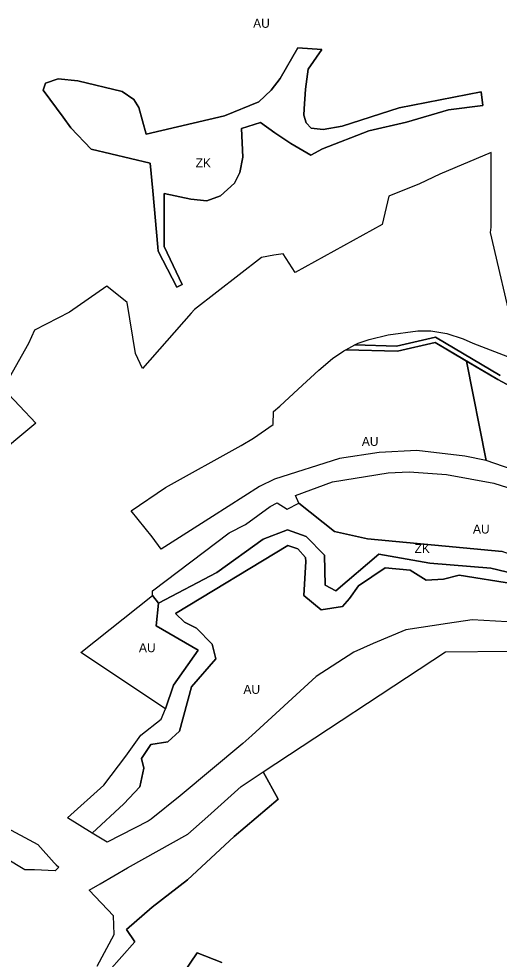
# Model space of a CAD drawing. Extents: x -521261 to -517465, y -1182764 to -1179456.
# Drawn here: x -518978 to -518710, y -1182068 to -1181544 of the extents above; entities that cross this region are included whole.
import ezdxf

# ---------------------------------------------------------------- set-up
doc = ezdxf.new("R2010")
doc.units = 0
for name, color, linetype in [('90640013', 7, 'Continuous'), ('90710013', 7, 'Continuous'), ('90750013', 7, 'Continuous')]:
    doc.layers.add(name, color=color, linetype=linetype)

msp = doc.modelspace()

# ---------------------------------------------------------------- linework, layer by layer
at = {"layer": '90640013'}
for points in [[(-518701.51, -1181750.01), (-518711.17, -1181744.79), (-518746.18, -1181724.23), (-518767.13, -1181729.02), (-518795.95, -1181728.17), (-518790.82, -1181725.54), (-518767.59, -1181726.19), (-518745.97, -1181721.22), (-518709.95, -1181742.54)], [(-518702.42, -1181858.59), (-518732.72, -1181853.68), (-518741.51, -1181856.01), (-518751.19, -1181856.52), (-518760.12, -1181851.01), (-518773.96, -1181849.7), (-518788.84, -1181859.75), (-518793.87, -1181866.71), (-518797.84, -1181871.11), (-518809.69, -1181873.09), (-518819.36, -1181864.98), (-518818.14, -1181846.17), (-518818.45, -1181843.81), (-518822.57, -1181839.04), (-518828.29, -1181837.22), (-518890.78, -1181874.99), (-518885.85, -1181879.81), (-518879.15, -1181883.26), (-518870.33, -1181892.11), (-518868.33, -1181900.31), (-518881.83, -1181915.88), (-518888.56, -1181940.6), (-518895.16, -1181946.6), (-518904.62, -1181947.99), (-518909.68, -1181955.8), (-518908.47, -1181961.1), (-518910.69, -1181971.61), (-518919.62, -1181981.1), (-518937.284, -1181997.298), (-518951.03, -1181988.87), (-518930.7, -1181970.59), (-518918.49, -1181954.45), (-518910.09, -1181942.77), (-518898.82, -1181933.95), (-518896.41, -1181928.2), (-518892.01, -1181914.91), (-518878.22, -1181895.5), (-518901.61, -1181881.85), (-518900.37, -1181869.35), (-518867.86, -1181852.31), (-518841.91, -1181833.59), (-518828.36, -1181828.4), (-518818.1, -1181832.25), (-518807.78, -1181842.57), (-518807.36, -1181859.37), (-518801.4, -1181862.37), (-518777.61, -1181841.96), (-518749.02, -1181847.06), (-518715.11, -1181849.85), (-518689.48, -1181855.99)], [(-519007.07, -1181982.5), (-518967.52, -1182003.69), (-518958.48, -1182013.83), (-518957.23, -1182014.96), (-518955.79, -1182016.24), (-518957.82, -1182018.26), (-518969.43, -1182017.88), (-518974.73, -1182017.76), (-519005.47, -1181999.42)]]:
    msp.add_lwpolyline(points, dxfattribs=at)
at = {"layer": '90710013'}
for points in [[(-518897.142, -1181668.909), (-518897.14, -1181670.68), (-518887.03, -1181691.88), (-518890.06, -1181693.33), (-518900.43, -1181673.23), (-518900.63, -1181671.03), (-518903.535, -1181639.789), (-518904.97, -1181624.36), (-518937.761, -1181616.586), (-518949.13, -1181604.61), (-518953.44, -1181598.74), (-518964.49, -1181583.72), (-518963.28, -1181579.75), (-518956.2, -1181577.33), (-518945.33, -1181578.54), (-518920.48, -1181584.41), (-518914.09, -1181588.9), (-518911.33, -1181593.39), (-518907.13, -1181608.19), (-518863.52, -1181597.88), (-518844.36, -1181590.11), (-518837.46, -1181583.72), (-518832.45, -1181577.16), (-518822.58, -1181560.08), (-518809.196, -1181560.942), (-518816.92, -1181571.98), (-518818.3, -1181583.03), (-518819.088, -1181594.127), (-518819.33, -1181597.53), (-518817.95, -1181601.85), (-518815.19, -1181604.79), (-518808.63, -1181605.65), (-518797.93, -1181603.75), (-518766.17, -1181593.56), (-518720.538, -1181584.665), (-518719.53, -1181592.27), (-518738.67, -1181594.7), (-518762.01, -1181601.41), (-518783.16, -1181606.24), (-518808.96, -1181616.3), (-518815.343, -1181619.949), (-518826.58, -1181613.42), (-518835.56, -1181607.38), (-518843.392, -1181601.735), (-518853.966, -1181605.045), (-518853.34, -1181621.02), (-518855.06, -1181629.48), (-518858, -1181635.52), (-518865.76, -1181642.43), (-518873.36, -1181645.36), (-518882.33, -1181644.33), (-518897.177, -1181641.151)], [(-518595.57, -1181761.58), (-518573.313, -1181774.703), (-518611.95, -1181784.61), (-518631.48, -1181785.91), (-518658.29, -1181781.74), (-518689.53, -1181773.67), (-518693.056, -1181798.326), (-518717.64, -1181789.82), (-518728.706, -1181734.492), (-518711.17, -1181744.79), (-518701.51, -1181750.01), (-518690.65, -1181759.52), (-518667.99, -1181770.25), (-518653.59, -1181771.67), (-518605.06, -1181761.8)]]:
    msp.add_lwpolyline(points, close=True, dxfattribs=at)
for points in [[(-518689.48, -1181855.99), (-518715.11, -1181849.85), (-518749.02, -1181847.06), (-518777.61, -1181841.96), (-518801.4, -1181862.37), (-518807.36, -1181859.37), (-518807.78, -1181842.57), (-518818.1, -1181832.25), (-518828.36, -1181828.4), (-518841.91, -1181833.59), (-518867.86, -1181852.31), (-518900.37, -1181869.35), (-518903.7, -1181865), (-518903.59, -1181862.37), (-518860.83, -1181830.07), (-518851.82, -1181825.53), (-518838.05, -1181815.43), (-518834.2, -1181813.52), (-518828.65, -1181816.89), (-518822.01, -1181813.66), (-518802.16, -1181829.32), (-518783.87, -1181833.43), (-518708.84, -1181840.52)], [(-518928.06, -1182074.15), (-518913.53, -1182057.93), (-518918.106, -1182050.945), (-518903.79, -1182038.57), (-518884.14, -1182023.3), (-518858.18, -1181999.19), (-518833.62, -1181978.44), (-518841.96, -1181963.21), (-518740.3, -1181896.33), (-518704.59, -1181895.96), (-518690.9, -1181913.09), (-518675.7, -1181927.23), (-518663.75, -1181934.22), (-518547.12, -1181985.79), (-518530.56, -1182016.35), (-518517.09, -1182044.24), (-518510.09, -1182043.38), (-518444.47, -1182035.28), (-518420.88, -1182053.43), (-518424.84, -1182054.69), (-518444.19, -1182063.4), (-518462.82, -1182099.41)], [(-518865.04, -1182069.45), (-518878.76, -1182064.07), (-518890.47, -1182081.22)]]:
    msp.add_lwpolyline(points, dxfattribs=at)
at = {"layer": '90750013'}
for points in [[(-518897.14, -1181670.68), (-518897.142, -1181668.909), (-518897.177, -1181641.151), (-518882.33, -1181644.33), (-518873.36, -1181645.36), (-518865.76, -1181642.43), (-518858, -1181635.52), (-518855.06, -1181629.48), (-518853.34, -1181621.02), (-518853.966, -1181605.045), (-518843.392, -1181601.735), (-518835.56, -1181607.38), (-518826.58, -1181613.42), (-518815.343, -1181619.949), (-518808.96, -1181616.3), (-518783.16, -1181606.24), (-518762.01, -1181601.41), (-518738.67, -1181594.7), (-518719.53, -1181592.27), (-518720.538, -1181584.665), (-518766.17, -1181593.56), (-518797.93, -1181603.75), (-518808.63, -1181605.65), (-518815.19, -1181604.79), (-518817.95, -1181601.85), (-518819.33, -1181597.53), (-518819.088, -1181594.127), (-518818.3, -1181583.03), (-518816.92, -1181571.98), (-518809.196, -1181560.942), (-518822.58, -1181560.08), (-518832.45, -1181577.16), (-518837.46, -1181583.72), (-518844.36, -1181590.11), (-518863.52, -1181597.88), (-518907.13, -1181608.19), (-518911.33, -1181593.39), (-518914.09, -1181588.9), (-518920.48, -1181584.41), (-518945.33, -1181578.54), (-518956.2, -1181577.33), (-518963.28, -1181579.75), (-518964.49, -1181583.72), (-518953.44, -1181598.74), (-518949.13, -1181604.61), (-518937.761, -1181616.586), (-518904.97, -1181624.36), (-518903.535, -1181639.789), (-518900.63, -1181671.03), (-518900.43, -1181673.23), (-518890.06, -1181693.33), (-518887.03, -1181691.88)], [(-518903.79, -1181832.41), (-518915.57, -1181817.81), (-518896.38, -1181804.98), (-518854.32, -1181781.51), (-518847.36, -1181777.51), (-518836.33, -1181769.91), (-518836.24, -1181762.63), (-518832.75, -1181759.58), (-518822.44, -1181750.08), (-518810.95, -1181739.54), (-518803.36, -1181732.99), (-518797.09, -1181728.75), (-518795.95, -1181728.17), (-518767.13, -1181729.02), (-518746.18, -1181724.23), (-518728.706, -1181734.492), (-518717.64, -1181789.82), (-518729.66, -1181787.39), (-518756.26, -1181784.25), (-518777.38, -1181785.37), (-518799.44, -1181788.82), (-518835.59, -1181800.36), (-518844.06, -1181804.35), (-518870.2, -1181821.05), (-518898.74, -1181839.23)], [(-518620.85, -1181848.06), (-518597.74, -1181856.58), (-518627.84, -1181863.67), (-518653.23, -1181864.79), (-518673.3, -1181859.85), (-518689.43, -1181847.62), (-518708.84, -1181840.52), (-518783.87, -1181833.43), (-518802.16, -1181829.32), (-518822.01, -1181813.66), (-518823.91, -1181809.28), (-518803.25, -1181801.73), (-518772.27, -1181796.81), (-518760.7, -1181796.26), (-518739.83, -1181797.72), (-518713.38, -1181802.54), (-518694.2, -1181808.7), (-518676.08, -1181816.9), (-518635.51, -1181841.21)], [(-518896.41, -1181928.2), (-518943.53, -1181896.7), (-518903.7, -1181865), (-518900.37, -1181869.35), (-518901.61, -1181881.85), (-518878.22, -1181895.5), (-518892.01, -1181914.91)]]:
    msp.add_lwpolyline(points, close=True, dxfattribs=at)
for points in [[(-518702.073, -1181719.351), (-518715.36, -1181662.99), (-518714.9, -1181659.89), (-518714.97, -1181618.35), (-518743.57, -1181630.46), (-518754.77, -1181635.75), (-518771.87, -1181642.78), (-518775.63, -1181658.39), (-518824.23, -1181685.21), (-518830.77, -1181674.88), (-518835.98, -1181675.62), (-518842.97, -1181676.88), (-518880.2, -1181705.76), (-518882.14, -1181707.91), (-518909.12, -1181738.67), (-518913.06, -1181730.29), (-518917.81, -1181701.96), (-518929.04, -1181692.85), (-518949.96, -1181707.37), (-518969.31, -1181717.27), (-518972.73, -1181724.81), (-518986.79, -1181749.85), (-518968.7, -1181769.11), (-518993.46, -1181789.66)], [(-518709.95, -1181742.54), (-518745.97, -1181721.22), (-518767.59, -1181726.19), (-518790.82, -1181725.54), (-518789.03, -1181724.62), (-518782.86, -1181722.48), (-518772.24, -1181719.87), (-518755.74, -1181717.72), (-518748.48, -1181717.72), (-518739.68, -1181719.15), (-518730.52, -1181722.04), (-518725.19, -1181724.49), (-518698.65, -1181734.68)], [(-518692.94, -1181880.52), (-518725.49, -1181878.51), (-518739.28, -1181880.59), (-518762.52, -1181884.14), (-518780.73, -1181891.86), (-518791.39, -1181896.52), (-518812.53, -1181910.12), (-518848.27, -1181943.05), (-518853.28, -1181947.39), (-518888.19, -1181976.5), (-518904.36, -1181989.62), (-518906.12, -1181990.72), (-518928.98, -1182002.39), (-518937.284, -1181997.298), (-518919.62, -1181981.1), (-518910.69, -1181971.61), (-518908.47, -1181961.1), (-518909.68, -1181955.8), (-518904.62, -1181947.99), (-518895.16, -1181946.6), (-518888.56, -1181940.6), (-518881.83, -1181915.88), (-518868.33, -1181900.31), (-518870.33, -1181892.11), (-518879.15, -1181883.26), (-518885.85, -1181879.81), (-518890.78, -1181874.99), (-518828.29, -1181837.22), (-518822.57, -1181839.04), (-518818.45, -1181843.81), (-518818.14, -1181846.17), (-518819.36, -1181864.98), (-518809.69, -1181873.09), (-518797.84, -1181871.11), (-518793.87, -1181866.71), (-518788.84, -1181859.75), (-518773.96, -1181849.7), (-518760.12, -1181851.01), (-518751.19, -1181856.52), (-518741.51, -1181856.01), (-518732.72, -1181853.68), (-518702.42, -1181858.59)], [(-518934.385, -1182071.457), (-518925.034, -1182053.763), (-518925.412, -1182043.463), (-518939.004, -1182029.096), (-518932.82, -1182025.58), (-518917.64, -1182016.73), (-518883.86, -1181997.98), (-518872.89, -1181988.08), (-518854.3, -1181971.43), (-518841.96, -1181963.21), (-518833.62, -1181978.44), (-518858.18, -1181999.19), (-518884.14, -1182023.3), (-518903.79, -1182038.57), (-518918.106, -1182050.945), (-518913.53, -1182057.93), (-518928.06, -1182074.15)], [(-518890.47, -1182081.22), (-518878.76, -1182064.07), (-518865.04, -1182069.45)]]:
    msp.add_lwpolyline(points, dxfattribs=at)

# ---------------------------------------------------------------- texts
at = {"layer": '90710013'}
for p in [(-518879.624, -1181626.705), (-518757.627, -1181841.435)]:
    msp.add_text('ZK', height=5, rotation=0, dxfattribs=at).set_placement(p)
at = {"layer": '90750013'}
for rotation, p in [(360, (-518847.556, -1181548.94)), (0, (-518725.07, -1181830.525)), (0, (-518911.203, -1181896.6)), (0, (-518852.97, -1181919.805))]:
    msp.add_text('AU', height=5, rotation=rotation, dxfattribs=at).set_placement(p)
msp.add_text('AU', height=5, dxfattribs=at).set_placement((-518786.986, -1181781.73))

doc.saveas('drawing.dxf')
